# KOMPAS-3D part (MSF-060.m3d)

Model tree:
1. Ось X
2. Ось Y
3. Ось Z
4. Начало координат  (labels: Операция без истории:1)

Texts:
  Линия-выноска #1
  Линия-выноска #2
  Линия-выноска #3
  Отклонения формы и база
  Марка координационной оси
  Марка/позиционное обозначение с линией-выноской
  Марка/позиционное обозначение на линии
  Марка/позиционное обозначение без линии-выноски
